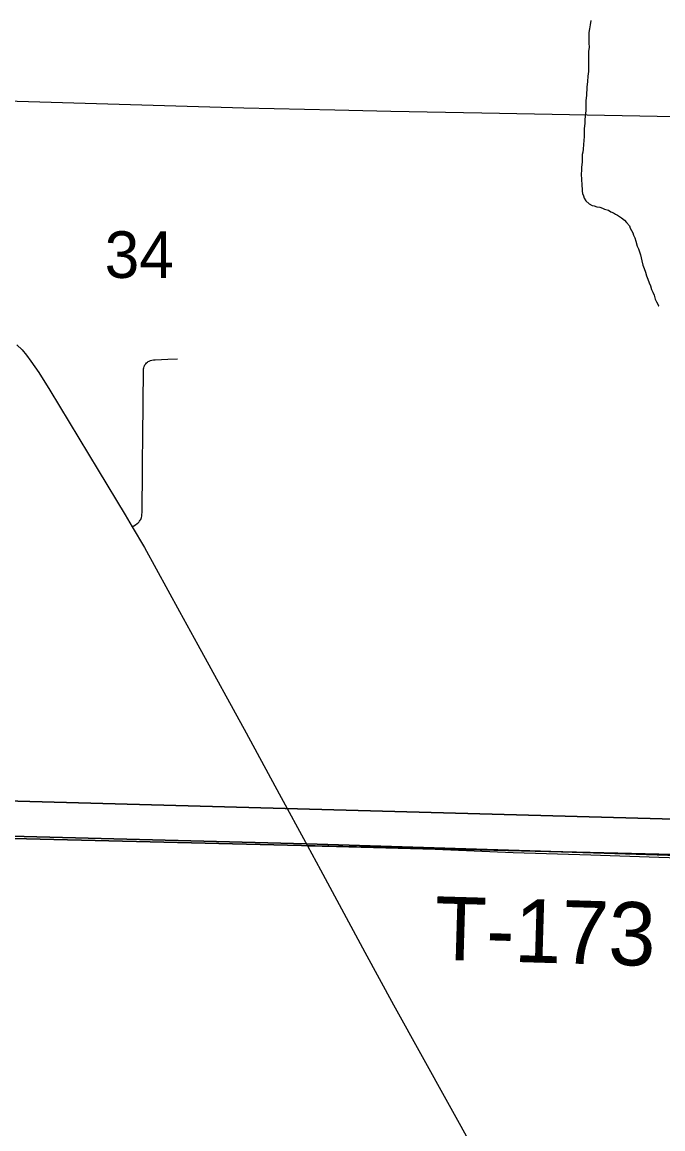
# Model space of a CAD drawing. Extents: x 0 to 68, y 0 to 52.9.
# Drawn here: x 47.485 to 48.093, y 34.94 to 35.989 of the extents above; entities that cross this region are included whole.
import ezdxf

# ---------------------------------------------------------------- set-up
doc = ezdxf.new("R2010")
doc.units = 0
for name, color, linetype in [('Default', 7, 'Continuous'), ('GM_X_Minor_River', 7, 'Continuous'), ('GM_X_State_Route', 7, 'Continuous'), ('GM_X_Township', 7, 'Continuous'), ('GM_X_Township_Road', 7, 'Continuous'), ('GM_X_Township_Road_Text', 7, 'Continuous')]:
    doc.layers.add(name, color=color, linetype=linetype)

msp = doc.modelspace()

# ---------------------------------------------------------------- linework, layer by layer
at = {"layer": 'Default'}
for points in [[(47.0429, 36.5865), (48.3843, 36.5523), (48.3458, 35.227), (47.008, 35.2636)], [(48.1401, 36.2463), (48.1151, 35.1997), (47.0588, 35.2253), (47.0762, 36.2748)], [(47.008, 35.2636), (48.3458, 35.227), (48.3149, 33.9086), (46.979, 33.9387)], [(47.0392, 35.2259), (47.0588, 35.2253), (48.1151, 35.1997), (48.0815, 34.1703), (47.0084, 34.1977)]]:
    msp.add_lwpolyline(points, close=True, dxfattribs=at)
at = {"layer": 'GM_X_Minor_River'}
msp.add_lwpolyline([(48.0242, 35.9902), (48.0238, 35.9862), (48.0229, 35.9822), (48.0225, 35.979), (48.0224, 35.9766), (48.0224, 35.9738), (48.0223, 35.9689), (48.0227, 35.9649), (48.0222, 35.9609), (48.0222, 35.9573), (48.0221, 35.9529), (48.0221, 35.9489), (48.022, 35.9452), (48.022, 35.942), (48.0215, 35.9376), (48.0211, 35.9324), (48.0206, 35.9272), (48.0201, 35.9191), (48.0196, 35.9143), (48.0196, 35.9103), (48.0195, 35.9083), (48.0195, 35.9055), (48.0191, 35.9015), (48.0186, 35.8967), (48.0185, 35.8926), (48.0181, 35.8878), (48.018, 35.8802), (48.0175, 35.8726), (48.017, 35.8682), (48.0166, 35.8654), (48.0162, 35.8633), (48.0161, 35.8601), (48.0161, 35.8561), (48.0156, 35.8513), (48.0156, 35.8477), (48.0151, 35.8453), (48.0154, 35.8388), (48.0158, 35.8352), (48.0158, 35.8332), (48.0162, 35.8312), (48.0161, 35.8284), (48.0165, 35.8264), (48.0173, 35.824), (48.0181, 35.8219), (48.0196, 35.8195), (48.0228, 35.8166), (48.0256, 35.815), (48.0276, 35.8146), (48.03, 35.8137), (48.0329, 35.8133), (48.0353, 35.8125), (48.0373, 35.8116), (48.0409, 35.8104), (48.0433, 35.8091), (48.0457, 35.8079), (48.0477, 35.8067), (48.0497, 35.8058), (48.0533, 35.8034), (48.0561, 35.8009), (48.0581, 35.7989), (48.0608, 35.7957), (48.0616, 35.7936), (48.0628, 35.7912), (48.064, 35.7892), (48.0647, 35.7868), (48.0659, 35.7843), (48.0671, 35.7811), (48.0682, 35.7763), (48.0694, 35.7738), (48.0714, 35.7682), (48.0725, 35.7626), (48.0737, 35.7585), (48.0748, 35.7553), (48.076, 35.7517), (48.0772, 35.7484), (48.0783, 35.7452), (48.0795, 35.7416), (48.0807, 35.7387), (48.0818, 35.7355), (48.083, 35.7327), (48.0842, 35.7299), (48.0853, 35.7262), (48.0865, 35.7238), (48.0877, 35.7214), (48.0885, 35.7198), (48.0889, 35.7198)], dxfattribs=at)
at = {"layer": 'GM_X_State_Route'}
msp.add_lwpolyline([(47.4802, 35.6829), (47.4852, 35.6781), (47.4894, 35.673), (47.4936, 35.6674), (47.5009, 35.6568), (47.5114, 35.64), (47.5573, 35.5642), (47.5829, 35.522), (47.5896, 35.5106), (47.6011, 35.4908), (47.6344, 35.4304), (47.6518, 35.3988), (47.6977, 35.3154), (47.729, 35.2576), (47.7558, 35.2082), (47.7681, 35.1854), (47.8102, 35.1074), (47.8373, 35.0576), (47.9156, 34.9163)], dxfattribs=at)
at = {"layer": 'GM_X_Township'}
for points in [[(49.6501, 35.1479), (49.27, 35.1583), (49.1679, 35.1597), (48.6476, 35.1787), (48.1174, 35.1987), (47.7547, 35.2101), (47.0487, 35.2284), (46.5224, 35.238), (45.9992, 35.2545), (45.9849, 35.2547), (45.1961, 35.2737)], [(45.1961, 35.2737), (45.9849, 35.2547), (45.9992, 35.2545), (46.5224, 35.238), (47.0487, 35.2284), (47.7547, 35.2101), (48.1174, 35.1987), (48.6476, 35.1787), (49.1679, 35.1597), (49.1465, 34.5262), (49.1402, 34.3268), (49.1301, 33.8729), (49.1238, 33.6102), (49.0976, 32.5488), (49.0801, 32.0211), (49.0691, 31.4938), (49.0618, 31.1431)]]:
    msp.add_lwpolyline(points, dxfattribs=at)
at = {"layer": 'GM_X_Township_Road'}
for points in [[(47.026, 35.9278), (47.2073, 35.9225), (47.3836, 35.9167), (47.6954, 35.9074), (47.7815, 35.9055), (47.8348, 35.9042), (47.921, 35.9029), (48.2369, 35.8967), (48.3657, 35.894)], [(47.5896, 35.5106), (47.5926, 35.5124), (47.5943, 35.5136), (47.5951, 35.5143), (47.5961, 35.5153), (47.5966, 35.5158), (47.5972, 35.5168), (47.5977, 35.5175), (47.5981, 35.5184), (47.5983, 35.5193), (47.5986, 35.5205), (47.5988, 35.5221), (47.5989, 35.524), (47.5989, 35.5263), (47.5991, 35.5337), (47.5991, 35.5375), (47.5992, 35.5515), (47.5994, 35.575), (47.5995, 35.5934), (47.5998, 35.6301), (47.6002, 35.6564), (47.6003, 35.6583), (47.6003, 35.659), (47.6004, 35.6602), (47.6006, 35.661), (47.6009, 35.6623), (47.6012, 35.6631), (47.6016, 35.6639), (47.6024, 35.665), (47.6032, 35.6658), (47.6039, 35.6665), (47.6047, 35.667), (47.6057, 35.6675), (47.6069, 35.668), (47.6082, 35.6683), (47.6097, 35.6686), (47.6114, 35.6688), (47.6233, 35.6693), (47.6325, 35.6697)], [(47.7558, 35.2082), (47.7831, 35.2077), (47.8768, 35.205), (47.9507, 35.202), (48.0242, 35.1997), (48.0889, 35.1974), (48.1183, 35.1966)]]:
    msp.add_lwpolyline(points, dxfattribs=at)

# ---------------------------------------------------------------- texts
at = {"layer": 'Default'}
msp.add_text('34', height=0.0442, rotation=0, dxfattribs=at).set_placement((47.5634, 35.7463))
at = {"layer": 'GM_X_Township_Road_Text'}
msp.add_text('T-173', height=0.06, rotation=358.3152, dxfattribs=at).set_placement((47.8754, 35.1005))

doc.saveas('drawing.dxf')
